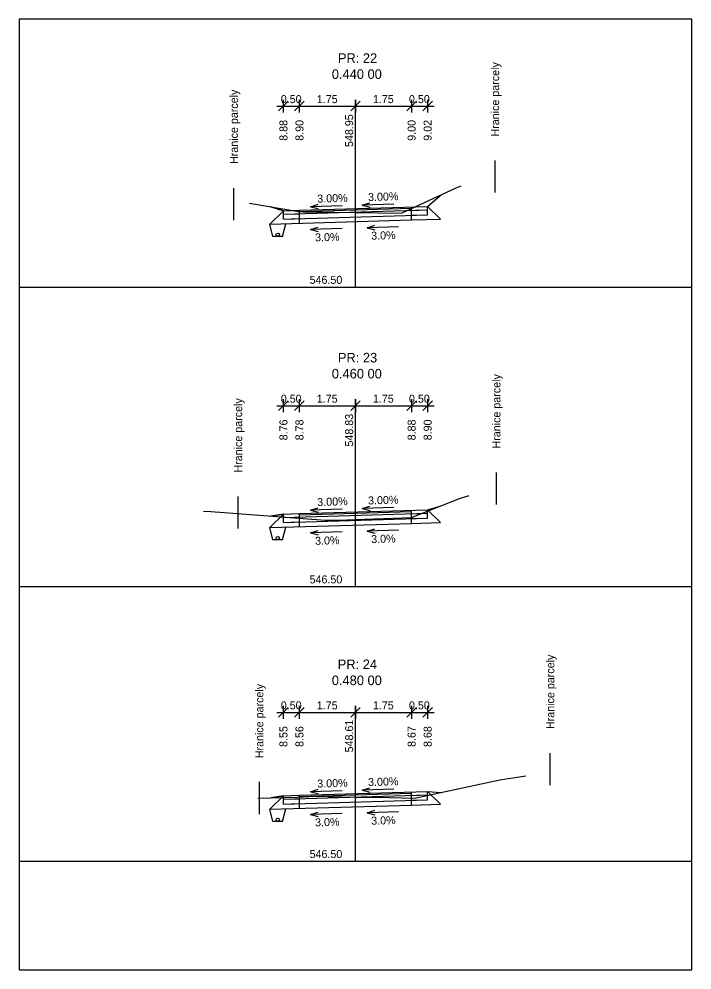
# Model space of a CAD drawing. Extents: x -603737 to -603383, y -1112154 to -1112124.
# Drawn here: x -603530.18 to -603509.18, y -1112153.84 to -1112124.14 of the extents above; entities that cross this region are included whole.
import ezdxf

# ---------------------------------------------------------------- set-up
doc = ezdxf.new("R2010")
doc.units = 0
for name, color, linetype in [('_křivky z hran', 7, 'Continuous'), ('_netisk', 7, 'Continuous'), ('C3D_Podsestava-Popis', 7, 'Continuous'), ('C3D_PP-Popisek', 7, 'Continuous'), ('C3D_PR', 7, 'Continuous'), ('C3D_ZPR', 7, 'Continuous'), ('Default', 7, 'Continuous'), ('konstrukce', 7, 'Continuous')]:
    doc.layers.add(name, color=color, linetype=linetype)

# ---------------------------------------------------------------- blocks, each defined once
blk = doc.blocks.new('_Oblique')
at = {"layer": 'Default'}
blk.add_line((-0.5, -0.5), (0.5, 0.5), dxfattribs=at)
blk = doc.blocks.new('AeccTickLine')
at = {"layer": 'Default'}
blk.add_line((0, 1), (0, -1), dxfattribs=at)

msp = doc.modelspace()

# ---------------------------------------------------------------- linework, layer by layer
at = {"layer": '_netisk'}
msp.add_lwpolyline([(-603530.183, -1112153.84), (-603509.183, -1112153.84), (-603509.183, -1112124.14), (-603530.183, -1112124.14)], close=True, dxfattribs=at)
at = {"layer": 'C3D_Podsestava-Popis'}
for p, q in [((-603522.133, -1112126.861), (-603519.683, -1112126.861)), ((-603519.683, -1112126.861), (-603517.233, -1112126.861)), ((-603519.683, -1112128.06), (-603519.683, -1112127.011)), ((-603522.133, -1112136.217), (-603519.683, -1112136.217)), ((-603519.683, -1112136.217), (-603517.233, -1112136.217)), ((-603519.683, -1112137.536), (-603519.683, -1112136.367)), ((-603522.133, -1112145.794), (-603519.683, -1112145.794)), ((-603519.683, -1112145.794), (-603517.233, -1112145.794)), ((-603519.683, -1112146.33), (-603519.683, -1112145.944))]:
    msp.add_line(p, q, dxfattribs=at)
at = {"layer": 'C3D_PP-Popisek'}
for p, q in [((-603521.086, -1112130.002), (-603520.85, -1112129.926)), ((-603520.102, -1112129.972), (-603521.086, -1112130.002)), ((-603521.086, -1112130.002), (-603520.846, -1112130.063)), ((-603519.475, -1112129.953), (-603519.238, -1112129.878)), ((-603518.491, -1112129.924), (-603519.475, -1112129.953)), ((-603519.475, -1112129.953), (-603519.234, -1112130.014)), ((-603521.086, -1112130.712), (-603520.85, -1112130.636)), ((-603520.102, -1112130.682), (-603521.086, -1112130.712)), ((-603521.086, -1112130.712), (-603520.846, -1112130.773)), ((-603519.322, -1112130.659), (-603519.085, -1112130.583)), ((-603518.338, -1112130.629), (-603519.322, -1112130.659)), ((-603519.322, -1112130.659), (-603519.081, -1112130.72)), ((-603519.475, -1112139.43), (-603519.238, -1112139.354)), ((-603521.086, -1112139.478), (-603520.85, -1112139.403)), ((-603520.102, -1112139.449), (-603521.086, -1112139.478)), ((-603521.086, -1112139.478), (-603520.846, -1112139.539)), ((-603518.491, -1112139.4), (-603519.475, -1112139.43)), ((-603519.475, -1112139.43), (-603519.234, -1112139.491)), ((-603521.086, -1112140.188), (-603520.85, -1112140.113)), ((-603520.102, -1112140.159), (-603521.086, -1112140.188)), ((-603521.086, -1112140.188), (-603520.846, -1112140.249)), ((-603519.322, -1112140.135), (-603519.085, -1112140.06)), ((-603518.338, -1112140.106), (-603519.322, -1112140.135)), ((-603519.322, -1112140.135), (-603519.081, -1112140.196)), ((-603521.086, -1112148.272), (-603520.85, -1112148.197)), ((-603520.102, -1112148.243), (-603521.086, -1112148.272)), ((-603521.086, -1112148.272), (-603520.846, -1112148.333)), ((-603519.475, -1112148.224), (-603519.238, -1112148.149)), ((-603518.491, -1112148.194), (-603519.475, -1112148.224)), ((-603519.475, -1112148.224), (-603519.234, -1112148.285)), ((-603519.322, -1112148.93), (-603519.085, -1112148.854)), ((-603521.086, -1112148.983), (-603520.85, -1112148.907)), ((-603520.102, -1112148.953), (-603521.086, -1112148.983)), ((-603521.086, -1112148.983), (-603520.846, -1112149.044)), ((-603518.338, -1112148.9), (-603519.322, -1112148.93)), ((-603519.322, -1112148.93), (-603519.081, -1112148.991))]:
    msp.add_line(p, q, dxfattribs=at)
at = {"layer": 'C3D_PR'}
for points in [[(-603522.99, -1112129.89), (-603521.457, -1112130.151), (-603521.166, -1112130.174), (-603520.971, -1112130.166), (-603519.683, -1112130.186), (-603518.243, -1112130.207), (-603516.543, -1112129.41), (-603516.386, -1112129.345)], [(-603524.425, -1112139.516), (-603524.332, -1112139.513), (-603520.629, -1112139.795), (-603520.225, -1112139.796), (-603519.683, -1112139.775), (-603517.931, -1112139.708), (-603516.442, -1112139.112), (-603516.173, -1112139.03), (-603516.146, -1112139.031)], [(-603522.73, -1112148.47), (-603521.507, -1112148.441), (-603520.952, -1112148.413), (-603519.683, -1112148.438), (-603518.647, -1112148.458), (-603517.844, -1112148.472), (-603515.18, -1112147.903), (-603514.363, -1112147.781)]]:
    msp.add_lwpolyline(points, dxfattribs=at)
at = {"layer": 'C3D_ZPR'}
for p, q in [((-603519.683, -1112132.511), (-603519.683, -1112127.011)), ((-603515.326, -1112129.56), (-603515.326, -1112128.56)), ((-603523.477, -1112130.418), (-603523.477, -1112129.418)), ((-603517.433, -1112129.992), (-603517.008, -1112129.628)), ((-603517.433, -1112129.992), (-603517.008, -1112129.628)), ((-603522.356, -1112130.55), (-603521.933, -1112130.127)), ((-603521.933, -1112130.127), (-603522.328, -1112130.003)), ((-603522.328, -1112130.003), (-603521.933, -1112130.127)), ((-603521.933, -1112130.237), (-603517.433, -1112130.102)), ((-603521.933, -1112130.127), (-603521.433, -1112130.112)), ((-603521.933, -1112130.387), (-603521.933, -1112130.127)), ((-603521.933, -1112130.387), (-603521.933, -1112130.127)), ((-603521.433, -1112130.112), (-603517.433, -1112129.992)), ((-603521.433, -1112130.152), (-603517.933, -1112130.047)), ((-603521.433, -1112130.522), (-603521.433, -1112130.112)), ((-603521.433, -1112130.222), (-603521.433, -1112130.152)), ((-603517.933, -1112130.047), (-603517.933, -1112130.007)), ((-603517.933, -1112130.417), (-603517.933, -1112130.007)), ((-603517.933, -1112130.117), (-603517.433, -1112130.102)), ((-603517.933, -1112130.267), (-603517.933, -1112130.117)), ((-603517.433, -1112130.252), (-603517.433, -1112129.992)), ((-603517.433, -1112130.252), (-603517.433, -1112129.992)), ((-603517.433, -1112129.992), (-603517.035, -1112130.39)), ((-603522.356, -1112130.55), (-603517.933, -1112130.417)), ((-603521.933, -1112130.237), (-603521.433, -1112130.222)), ((-603521.933, -1112130.387), (-603517.433, -1112130.252)), ((-603521.933, -1112130.387), (-603521.433, -1112130.372)), ((-603521.433, -1112130.522), (-603521.433, -1112130.372)), ((-603517.933, -1112130.267), (-603517.433, -1112130.252)), ((-603517.933, -1112130.417), (-603517.035, -1112130.39)), ((-603530.183, -1112132.511), (-603509.183, -1112132.511)), ((-603519.683, -1112141.867), (-603519.683, -1112136.367)), ((-603515.286, -1112139.304), (-603515.286, -1112138.304)), ((-603523.345, -1112140.056), (-603523.345, -1112139.056)), ((-603517.433, -1112139.468), (-603517.008, -1112139.339)), ((-603517.433, -1112139.468), (-603517.008, -1112139.339)), ((-603522.356, -1112140.026), (-603521.933, -1112139.603)), ((-603521.933, -1112139.603), (-603522.328, -1112139.666)), ((-603522.328, -1112139.666), (-603521.933, -1112139.603)), ((-603521.933, -1112139.713), (-603517.433, -1112139.578)), ((-603521.933, -1112139.603), (-603521.433, -1112139.588)), ((-603521.933, -1112139.863), (-603521.933, -1112139.603)), ((-603521.933, -1112139.863), (-603521.933, -1112139.603)), ((-603521.433, -1112139.588), (-603517.433, -1112139.468)), ((-603521.433, -1112139.628), (-603517.933, -1112139.523)), ((-603521.433, -1112139.998), (-603521.433, -1112139.588)), ((-603521.433, -1112139.698), (-603521.433, -1112139.628)), ((-603517.933, -1112139.523), (-603517.933, -1112139.483)), ((-603517.933, -1112139.893), (-603517.933, -1112139.483)), ((-603517.933, -1112139.593), (-603517.433, -1112139.578)), ((-603517.933, -1112139.743), (-603517.933, -1112139.593)), ((-603517.433, -1112139.728), (-603517.433, -1112139.468)), ((-603517.433, -1112139.728), (-603517.433, -1112139.468)), ((-603517.433, -1112139.468), (-603517.035, -1112139.867)), ((-603522.356, -1112140.026), (-603517.933, -1112139.893)), ((-603521.933, -1112139.713), (-603521.433, -1112139.698)), ((-603521.933, -1112139.863), (-603517.433, -1112139.728)), ((-603521.933, -1112139.863), (-603521.433, -1112139.848)), ((-603521.433, -1112139.998), (-603521.433, -1112139.848)), ((-603517.933, -1112139.743), (-603517.433, -1112139.728)), ((-603517.933, -1112139.893), (-603517.035, -1112139.867)), ((-603530.183, -1112141.867), (-603509.183, -1112141.867)), ((-603519.683, -1112150.444), (-603519.683, -1112145.944)), ((-603513.605, -1112148.065), (-603513.605, -1112147.065)), ((-603522.684, -1112148.969), (-603522.684, -1112147.969)), ((-603521.433, -1112148.383), (-603517.433, -1112148.263)), ((-603517.933, -1112148.318), (-603517.933, -1112148.278)), ((-603517.933, -1112148.688), (-603517.933, -1112148.278)), ((-603517.433, -1112148.523), (-603517.433, -1112148.263)), ((-603517.433, -1112148.523), (-603517.433, -1112148.263)), ((-603517.433, -1112148.263), (-603517.035, -1112148.661)), ((-603517.433, -1112148.263), (-603517.008, -1112148.294)), ((-603517.433, -1112148.263), (-603517.008, -1112148.294)), ((-603522.356, -1112148.821), (-603521.933, -1112148.398)), ((-603521.933, -1112148.398), (-603522.328, -1112148.46)), ((-603522.328, -1112148.46), (-603521.933, -1112148.398)), ((-603521.933, -1112148.508), (-603517.433, -1112148.373)), ((-603521.933, -1112148.398), (-603521.433, -1112148.383)), ((-603521.933, -1112148.658), (-603521.933, -1112148.398)), ((-603521.933, -1112148.658), (-603521.933, -1112148.398)), ((-603521.933, -1112148.508), (-603521.433, -1112148.493)), ((-603521.933, -1112148.658), (-603517.433, -1112148.523)), ((-603521.433, -1112148.423), (-603517.933, -1112148.318)), ((-603521.433, -1112148.793), (-603521.433, -1112148.383)), ((-603521.433, -1112148.493), (-603521.433, -1112148.423)), ((-603517.933, -1112148.388), (-603517.433, -1112148.373)), ((-603517.933, -1112148.538), (-603517.933, -1112148.388)), ((-603517.933, -1112148.538), (-603517.433, -1112148.523)), ((-603522.356, -1112148.821), (-603517.933, -1112148.688)), ((-603521.933, -1112148.658), (-603521.433, -1112148.643)), ((-603521.433, -1112148.793), (-603521.433, -1112148.643)), ((-603517.933, -1112148.688), (-603517.035, -1112148.661)), ((-603530.183, -1112150.444), (-603509.183, -1112150.444))]:
    msp.add_line(p, q, dxfattribs=at)
at = {"layer": 'konstrukce'}
for p, q in [((-603522.26, -1112130.935), (-603522.356, -1112130.55)), ((-603521.96, -1112130.935), (-603521.86, -1112130.535)), ((-603521.96, -1112130.935), (-603522.26, -1112130.935)), ((-603522.26, -1112140.411), (-603522.356, -1112140.026)), ((-603521.96, -1112140.411), (-603521.86, -1112140.011)), ((-603521.96, -1112140.411), (-603522.26, -1112140.411)), ((-603522.26, -1112149.206), (-603522.356, -1112148.821)), ((-603521.96, -1112149.206), (-603521.86, -1112148.806)), ((-603521.96, -1112149.206), (-603522.26, -1112149.206))]:
    msp.add_line(p, q, dxfattribs=at)
for centre in [(-603522.11, -1112130.875), (-603522.11, -1112140.351), (-603522.11, -1112149.146)]:
    msp.add_circle(centre, 0.05, dxfattribs=at)

# ---------------------------------------------------------------- block references
at = {"layer": '_křivky z hran', "rotation": 180}
for name, p, xscale, yscale in [('_Oblique', (-603521.933, -1112126.861), 0.3, 0.3), ('AeccTickLine', (-603521.933, -1112126.861), 0.2, 0.20000000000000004), ('_Oblique', (-603521.433, -1112126.861), 0.3, 0.3), ('AeccTickLine', (-603521.433, -1112126.861), 0.2, 0.20000000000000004), ('_Oblique', (-603519.683, -1112126.861), 0.3, 0.3), ('AeccTickLine', (-603519.683, -1112126.861), 0.2, 0.20000000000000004), ('_Oblique', (-603521.933, -1112136.217), 0.3, 0.3), ('AeccTickLine', (-603521.933, -1112136.217), 0.2, 0.20000000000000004), ('_Oblique', (-603521.433, -1112136.217), 0.3, 0.3), ('AeccTickLine', (-603521.433, -1112136.217), 0.2, 0.20000000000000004), ('_Oblique', (-603519.683, -1112136.217), 0.3, 0.3), ('AeccTickLine', (-603519.683, -1112136.217), 0.2, 0.20000000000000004), ('AeccTickLine', (-603521.933, -1112145.794), 0.2, 0.20000000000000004), ('AeccTickLine', (-603521.433, -1112145.794), 0.2, 0.20000000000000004), ('AeccTickLine', (-603519.683, -1112145.794), 0.2, 0.20000000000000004), ('_Oblique', (-603521.933, -1112145.794), 0.3, 0.3), ('_Oblique', (-603521.433, -1112145.794), 0.3, 0.3), ('_Oblique', (-603519.683, -1112145.794), 0.3, 0.3)]:
    msp.add_blockref(name, p, dxfattribs=dict(at, xscale=xscale, yscale=yscale))
at = {"layer": '_křivky z hran'}
for name, p, xscale, yscale in [('_Oblique', (-603519.683, -1112126.861), 0.3, 0.3), ('AeccTickLine', (-603519.683, -1112126.861), 0.2, 0.20000000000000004), ('_Oblique', (-603517.933, -1112126.861), 0.3, 0.3), ('AeccTickLine', (-603517.933, -1112126.861), 0.2, 0.20000000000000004), ('_Oblique', (-603517.433, -1112126.861), 0.3, 0.3), ('AeccTickLine', (-603517.433, -1112126.861), 0.2, 0.20000000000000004), ('_Oblique', (-603519.683, -1112136.217), 0.3, 0.3), ('AeccTickLine', (-603519.683, -1112136.217), 0.2, 0.20000000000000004), ('_Oblique', (-603517.933, -1112136.217), 0.3, 0.3), ('AeccTickLine', (-603517.933, -1112136.217), 0.2, 0.20000000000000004), ('_Oblique', (-603517.433, -1112136.217), 0.3, 0.3), ('AeccTickLine', (-603517.433, -1112136.217), 0.2, 0.20000000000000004), ('AeccTickLine', (-603519.683, -1112145.794), 0.2, 0.20000000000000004), ('AeccTickLine', (-603517.933, -1112145.794), 0.2, 0.20000000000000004), ('AeccTickLine', (-603517.433, -1112145.794), 0.2, 0.20000000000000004), ('_Oblique', (-603519.683, -1112145.794), 0.3, 0.3), ('_Oblique', (-603517.933, -1112145.794), 0.3, 0.3), ('_Oblique', (-603517.433, -1112145.794), 0.3, 0.3)]:
    msp.add_blockref(name, p, dxfattribs=dict(at, xscale=xscale, yscale=yscale))

# ---------------------------------------------------------------- texts
at = {"layer": 'C3D_Podsestava-Popis'}
for s, rotation, p in [('0.50', 360, (-603522.015, -1112126.767)), ('1.75', 360, (-603520.891, -1112126.767)), ('1.75', 360, (-603520.891, -1112126.767)), ('1.75', 360, (-603519.141, -1112126.767)), ('1.75', 360, (-603519.141, -1112126.767)), ('0.50', 360, (-603518.015, -1112126.767)), ('548.95', 90, (-603519.757, -1112128.138)), ('8.88', 90, (-603521.807, -1112127.943)), ('8.88', 90, (-603521.807, -1112127.943)), ('8.90', 90, (-603521.307, -1112127.943)), ('9.00', 90, (-603517.807, -1112127.943)), ('9.02', 90, (-603517.307, -1112127.942)), ('9.02', 90, (-603517.307, -1112127.942)), ('3.00%', 1.7184, (-603519.288, -1112129.827)), ('3.00%', 1.7184, (-603520.873, -1112129.876)), ('3.0%', 1.7184, (-603520.941, -1112131.087)), ('3.0%', 1.7184, (-603519.191, -1112131.034)), ('0.50', 360, (-603522.015, -1112136.123)), ('1.75', 360, (-603520.891, -1112136.123)), ('1.75', 360, (-603520.891, -1112136.123)), ('1.75', 360, (-603519.141, -1112136.123)), ('1.75', 360, (-603519.141, -1112136.123)), ('0.50', 360, (-603518.015, -1112136.123)), ('8.76', 90, (-603521.807, -1112137.299)), ('8.76', 90, (-603521.807, -1112137.299)), ('8.78', 90, (-603521.307, -1112137.299)), ('548.83', 90, (-603519.757, -1112137.493)), ('8.88', 90, (-603517.807, -1112137.299)), ('8.90', 90, (-603517.307, -1112137.298)), ('8.90', 90, (-603517.307, -1112137.298)), ('3.00%', 1.7184, (-603519.288, -1112139.303)), ('3.00%', 1.7184, (-603520.873, -1112139.352)), ('3.0%', 1.7184, (-603519.191, -1112140.51)), ('3.0%', 1.7184, (-603520.941, -1112140.563)), ('0.50', 360, (-603522.015, -1112145.7)), ('1.75', 360, (-603520.891, -1112145.7)), ('1.75', 360, (-603520.891, -1112145.7)), ('1.75', 360, (-603519.141, -1112145.7)), ('1.75', 360, (-603519.141, -1112145.7)), ('0.50', 360, (-603518.015, -1112145.7)), ('548.61', 90, (-603519.757, -1112147.045)), ('8.55', 90, (-603521.807, -1112146.876)), ('8.55', 90, (-603521.807, -1112146.876)), ('8.56', 90, (-603521.307, -1112146.875)), ('8.67', 90, (-603517.807, -1112146.875)), ('8.68', 90, (-603517.307, -1112146.876)), ('8.68', 90, (-603517.307, -1112146.876)), ('3.00%', 1.7184, (-603520.873, -1112148.146)), ('3.00%', 1.7184, (-603519.288, -1112148.098)), ('3.0%', 1.7184, (-603520.941, -1112149.357)), ('3.0%', 1.7184, (-603519.191, -1112149.305))]:
    msp.add_text(s, height=0.25, rotation=rotation, dxfattribs=at).set_placement(p)
at = {"layer": 'C3D_ZPR'}
for s, p in [('PR: 22', (-603520.233, -1112125.511)), ('0.440 00', (-603520.423, -1112126.011)), ('PR: 23', (-603520.233, -1112134.867)), ('0.460 00', (-603520.423, -1112135.367)), ('PR: 24', (-603520.238, -1112144.444)), ('0.480 00', (-603520.423, -1112144.944))]:
    msp.add_text(s, height=0.3, dxfattribs=at).set_placement(p)
for s, rotation, p in [('Hranice parcely', 90, (-603515.201, -1112127.81)), ('Hranice parcely', 90, (-603523.352, -1112128.668)), ('546.50', 360, (-603521.117, -1112132.411)), ('Hranice parcely', 90, (-603515.161, -1112137.554)), ('Hranice parcely', 90, (-603523.22, -1112138.306)), ('546.50', 360, (-603521.117, -1112141.767)), ('Hranice parcely', 90, (-603513.48, -1112146.315)), ('Hranice parcely', 90, (-603522.559, -1112147.228)), ('546.50', 360, (-603521.117, -1112150.344))]:
    msp.add_text(s, height=0.25, rotation=rotation, dxfattribs=at).set_placement(p)

doc.saveas('drawing.dxf')
